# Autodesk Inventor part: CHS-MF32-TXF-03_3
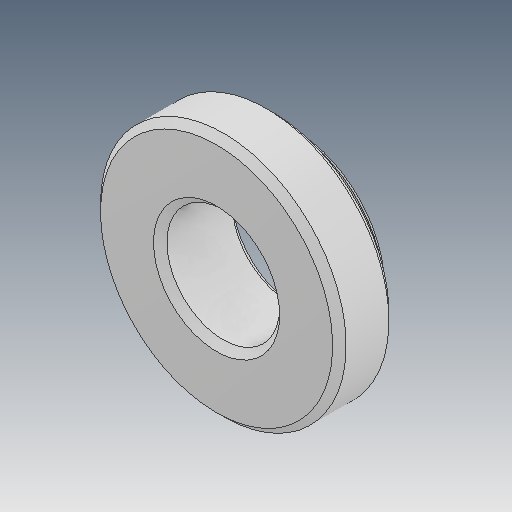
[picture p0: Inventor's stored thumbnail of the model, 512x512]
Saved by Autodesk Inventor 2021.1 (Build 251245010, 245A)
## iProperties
Created: 2021-05
Part Number: CHS-MF32-TXF-03_3
Material: Ogólny
Document SubType Name: Modeling
Designer: user
Density: 1 g/cm^3
Appearance: Domyślna
Author: user
Revision Number: ÈÎºÎ
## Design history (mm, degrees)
feature "ÊäÈë1"
node "Bryła1"
